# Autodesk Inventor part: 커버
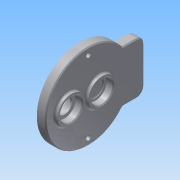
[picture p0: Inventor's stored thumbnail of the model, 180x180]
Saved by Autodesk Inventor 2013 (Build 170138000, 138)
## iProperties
Created: 2016-02
Part Number: 커버
Material: 알루미늄 6061
Document SubType Name: Modeling
Designer: mduedu
Density: 2.71 g/cm^3
Mass: 157.247 g
Surface Area: 178.476 cm^2
Volume: 58.0249 cm^3
Author: mduedu
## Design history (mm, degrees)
sketch "스케치1"
  geometry: C1 r 43 at (0, 0); 1 further point
  constraints: 1 centre point, 1 coincident
  dimensions: "d0" = 86 diameter of C1
extrude "돌출1" new body sketch "스케치1" distance "d1" = 9; taper "d2" = 0 deg
sketch "스케치2"
  geometry: C1 r 14 at (0, 11); 1 further point
  constraints: 1 centre point, 1 vertical alignment
  dimensions: "d3" = 28 diameter of C1; "d6" = 11 distance of C1.centre point (0, 0)
extrude "돌출2" join sketch "스케치2" distance "d7" = 3; taper "d8" = 0 deg
sketch "스케치3"
  geometry: C1 r 14 at (0, -20); 1 further point
  constraints: 1 centre point, 1 vertical alignment
  dimensions: "d9" = 28 diameter of C1; "d10" = 20 distance of C1.centre point (0, 0)
extrude "돌출3" join sketch "스케치3" distance "d11" = 3; taper "d12" = 0 deg
hole "구멍1" diameter "d15" = 22; stored, may be unused: countersink angle "d19" = 90 deg, drill point angle "d21" = 0 deg; dims "d13" = 10, "d14" = 10, "d16" = 6, "d17" = 4, "d18" = 2, "d20" = 7
hole "구멍2" diameter "d24" = 18; stored, may be unused: countersink angle "d28" = 90 deg, drill point angle "d30" = 0 deg; dims "d22" = 10, "d23" = 10, "d25" = 6, "d26" = 4, "d27" = 2, "d29" = 1
hole "구멍3" diameter "d33" = 22; stored, may be unused: countersink angle "d37" = 90 deg, drill point angle "d39" = 0 deg; dims "d34" = 6, "d35" = 4, "d36" = 2, "d38" = 7, "d73" = 10, "d74" = 10
sketch "스케치7"
  geometry: L1 (-26, 34.249)-(26, 34.249); L2 (26, 34.249)-(26, 56); L3 (26, 56)-(-26, 56); L4 (-26, 56)-(-26, 34.249); A1 r 43 centre (0, 0) between (-26, 34.249) and (26, 34.249) reference; 1 further point
  constraints: 8 end point, 2 parallel, 2 point on circle, 1 horizontal, 1 perpendicular
  dimensions: "d95" = 52 distance of L2.end L3.end; "d97" = 56 distance from line of L3 point (0, 0)
extrude "돌출5" join sketch "스케치7" stored distance "d98" = 10; taper "d99" = 0 deg
sketch "스케치4"
  geometry: C1 r 14 at (0, -20) reference; C2 r 18 at (0, -20); 1 further point
  constraints: 1 centre point, 1 coincident
  dimensions: "d40" = 36 diameter of C2
extrude "돌출4" join sketch "스케치4" distance "d41" = 4; taper "d42" = 0 deg
hole "구멍4" diameter "d45" = 22; stored, may be unused: countersink angle "d49" = 90 deg, drill point angle "d51" = 0 deg; dims "d43" = 10, "d44" = 10, "d46" = 6, "d47" = 4, "d48" = 2, "d50" = 7
hole "구멍5" diameter "d54" = 15; stored, may be unused: countersink angle "d58" = 90 deg, drill point angle "d60" = 0 deg; dims "d52" = 10, "d53" = 10, "d55" = 6, "d56" = 4, "d57" = 2, "d59" = 7
fillet "모깎기1" dims "d61" = 0.3
fillet "모깎기2" dims "d62" = 2
chamfer "모따기1" distance "d63" = 1; stored, may be unused: second distance "d64" = 2, angle "d65" = 45 deg
fillet "모깎기6" dims "d88" = 2
sketch "스케치5" dims "d67" = 72
  geometry: 4 further points
  constraints: 2 horizontal alignment, 1 coincident, 5 other
  dimensions: "d71" = 360 deg dimension on point (0, 0) point (-36, 0) (derived)
fillet "모깎기4" dims "d75" = 2
sketch "스케치6"
  geometry: 2 further points
hole "구멍6" sketch "스케치6" at (36, 0), (-36, 0) diameter "d76" = 4.5; stored, may be unused: countersink angle "d80" = 90 deg, drill point angle "d82" = 0 deg; dims "d77" = 6, "d78" = 8, "d79" = 4.6, "d81" = 8
fillet "모깎기7" dims "d100" = 8, "d101" = 2
chamfer "모따기2" distance "d90" = 1; stored, may be unused: second distance "d91" = 2, angle "d92" = 45 deg
node "솔리드1"
node "절단 모서리 투영1"
